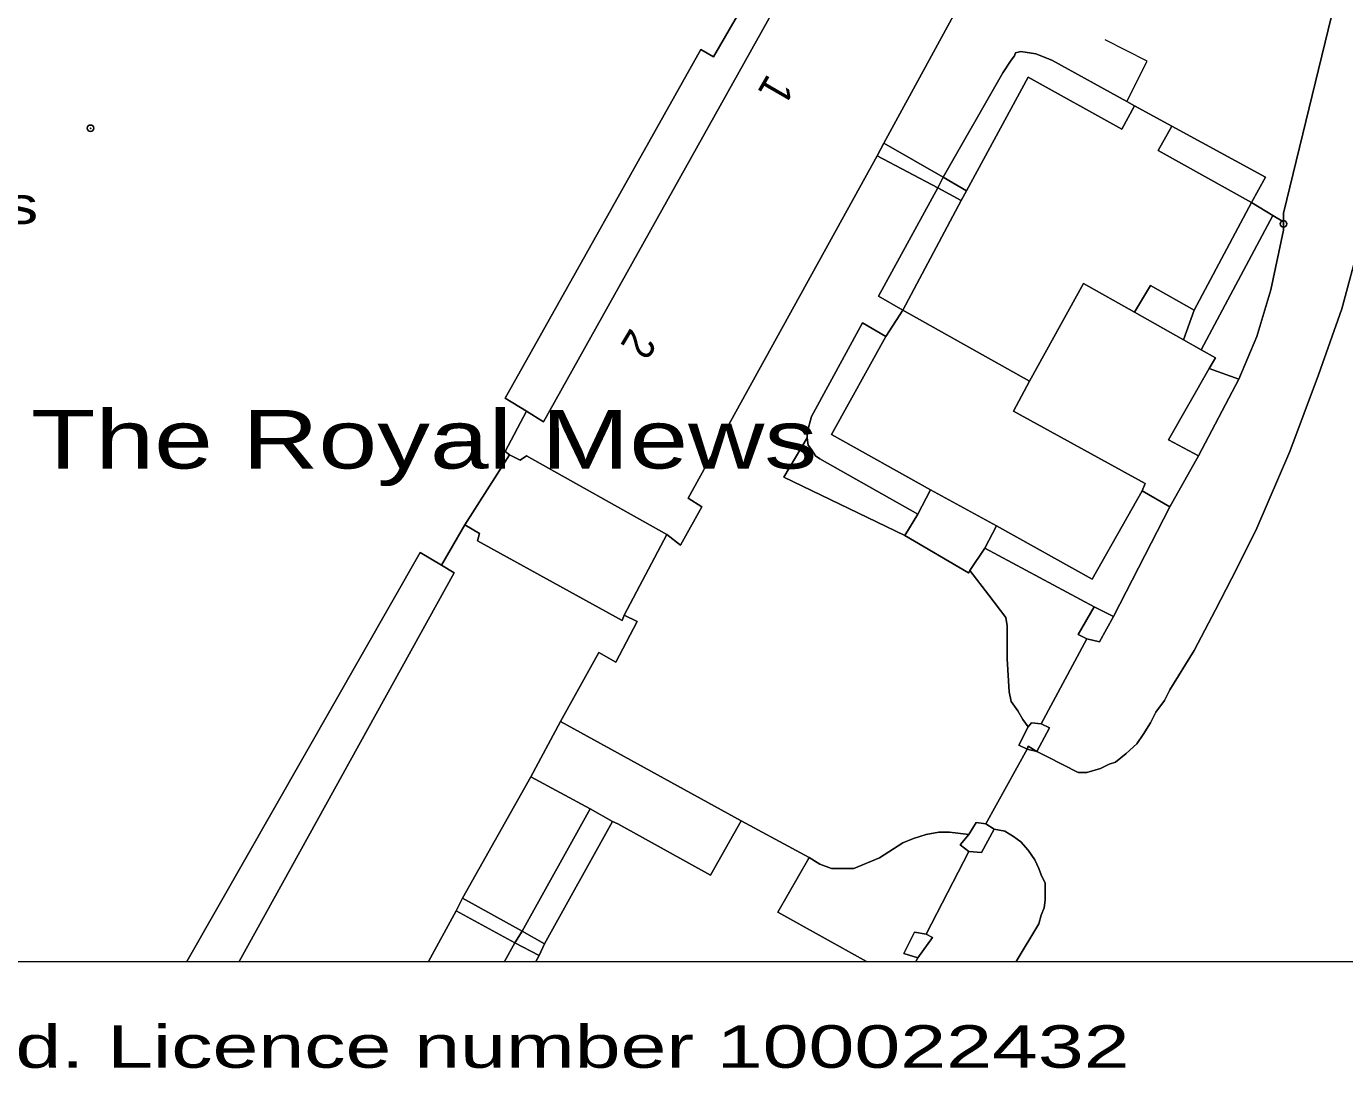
# Model space of a CAD drawing. Extents: x 528790 to 529292, y 179350 to 179856.
# Drawn here: x 528898.3 to 528960.3, y 179350.4 to 179400 of the extents above; entities that cross this region are included whole.
import ezdxf

# ---------------------------------------------------------------- set-up
doc = ezdxf.new("R2010")
doc.units = 0
doc.header["$LTSCALE"] = 0.6
doc.header["$PDMODE"] = 32
doc.header["$PDSIZE"] = 0.3
for name, color, linetype, lineweight in [('1', 7, 'Continuous', 13), ('2', 7, 'Continuous', 13), ('7', 7, 'Continuous', 13)]:
    doc.layers.add(name, color=color, linetype=linetype, lineweight=lineweight)
for name, color, linetype in [('3', 7, 'Continuous'), ('4', 7, 'Continuous'), ('5', 7, 'Continuous'), ('8', 7, 'Continuous')]:
    doc.layers.add(name, color=color, linetype=linetype)

msp = doc.modelspace()

# ---------------------------------------------------------------- linework, layer by layer
at = {"layer": '1'}
for points in [[(528897.956, 179356.024), (528905.826, 179356.024), (528916.8, 179375.25), (528917.8, 179374.65), (528918.9, 179376.55), (528921, 179379.85), (528920.8, 179380), (528921.8, 179381.9), (528920.8, 179382.5), (528930, 179398.9), (528930.6, 179398.55), (528931.9, 179400.8), (528911.446, 179412.309), (528912.253, 179413.743), (528911.257, 179414.303), (528910.45, 179412.87), (528908.12, 179408.74), (528900.05, 179413.29), (528902.38, 179417.42), (528903.061, 179418.631), (528902.369, 179419.02), (528901.688, 179417.809), (528881.8, 179429)], [(528943, 179402.55), (528938.6, 179394.5), (528941.4, 179392.9), (528944.2, 179397.8), (528944.6, 179398.4), (528944.75, 179398.6), (528944.8, 179398.75), (528945.05, 179398.8), (528945.75, 179398.7), (528946.5, 179398.4), (528950.029, 179396.454), (528950.4, 179396.25), (528952.15, 179395.3), (528956.55, 179392.9), (528955.9, 179391.7), (528956.903, 179391.098), (528957.4, 179390.8), (528957.4, 179391.2), (528959.95, 179401.7)], [(528959.95, 179401.7), (528957.4, 179391.2), (528957.4, 179390.8), (528957.4, 179390.4), (528956.8, 179387.6), (528956.15, 179385.4), (528955.3, 179383.4), (528953.4, 179379.8), (528952.05, 179377.4), (528949.4, 179372.25), (528948.75, 179371.05), (528948.15, 179371.2), (528946, 179367.2), (528946.4, 179367), (528945.8, 179365.9), (528946.3, 179365.65), (528947.75, 179364.9), (528948.15, 179364.9), (528948.8, 179365.1), (528949.2, 179365.3), (528949.5, 179365.4), (528950, 179365.8), (528950.5, 179366.25), (528950.8, 179366.7), (528951.15, 179367.25), (528951.4, 179367.75), (528951.8, 179368.3), (528952.05, 179368.8), (528953.2, 179370.65), (528954.2, 179372.55), (528955.2, 179374.5), (528956.15, 179376.4), (528957.7, 179380), (528959.05, 179383.6), (528960.15, 179386.7), (528961, 179389.9)], [(528961, 179389.9), (528960.15, 179386.7), (528959.05, 179383.6), (528957.7, 179380), (528956.15, 179376.4), (528955.2, 179374.5), (528954.2, 179372.55), (528953.2, 179370.65), (528952.05, 179368.8), (528951.8, 179368.3), (528951.4, 179367.75), (528951.15, 179367.25), (528950.8, 179366.7), (528950.5, 179366.25), (528950, 179365.8), (528949.5, 179365.4), (528949.2, 179365.3), (528948.8, 179365.1), (528948.15, 179364.9), (528947.75, 179364.9), (528946.3, 179365.65), (528945.8, 179365.9), (528945.35, 179366), (528943.4, 179362.5), (528943.8, 179362.25), (528944.3, 179362.15), (528944.7, 179361.9), (528945.05, 179361.65), (528945.4, 179361.25), (528945.7, 179360.8), (528945.9, 179360.4), (528946, 179360.1), (528946.2, 179359.7), (528946.2, 179358.9), (528946.15, 179358.55), (528946, 179358.2), (528945.9, 179357.8), (528944.836, 179356.024), (528961.131, 179356.024)]]:
    msp.add_lwpolyline(points, dxfattribs=at)
for points in [[(528938.3, 179393.9), (528938.6, 179394.5), (528943, 179402.55), (528942.6, 179402.8), (528936.95, 179405.85), (528936.4, 179406.15), (528935.95, 179405.3), (528922.6, 179381.4), (528921.8, 179381.9), (528920.8, 179380), (528921, 179379.85), (528921.5, 179379.6), (528921.8, 179379.8), (528928.4, 179376.1), (528929.05, 179375.6), (528930.05, 179377.4), (528929.4, 179377.8)], [(528921.8, 179381.9), (528922.6, 179381.4), (528935.95, 179405.3), (528934.8, 179405.95), (528931.9, 179400.8), (528930.6, 179398.55), (528930, 179398.9), (528920.8, 179382.5)], [(528950.4, 179396.25), (528950.029, 179396.454), (528946.5, 179398.4), (528945.75, 179398.7), (528945.05, 179398.8), (528944.8, 179398.75), (528944.75, 179398.6), (528944.6, 179398.4), (528944.2, 179397.8), (528941.4, 179392.9), (528942.5, 179392.25), (528945.4, 179397.6), (528949.8, 179395.15)], [(528945.45, 179383.3), (528948, 179387.9), (528950.4, 179386.55), (528951.15, 179387.8), (528953.2, 179386.65), (528955.9, 179391.7), (528951.5, 179394.15), (528952.15, 179395.3), (528950.4, 179396.25), (528949.8, 179395.15), (528945.4, 179397.6), (528942.5, 179392.25), (528942.25, 179391.8), (528939.5, 179386.65)], [(528952.15, 179395.3), (528951.5, 179394.15), (528955.9, 179391.7), (528956.55, 179392.9)], [(528941.4, 179392.9), (528938.6, 179394.5), (528938.3, 179393.9), (528941.15, 179392.4)], [(528939.5, 179386.65), (528938.35, 179387.3), (528941.15, 179392.4), (528938.3, 179393.9), (528929.4, 179377.8), (528930.05, 179377.4), (528929.05, 179375.6), (528928.4, 179376.1), (528926.4, 179372.3), (528927, 179372), (528926, 179370.1), (528925.2, 179370.55), (528923.4, 179367.3), (528931.899, 179362.632), (528935.088, 179360.906), (528935.6, 179360.6), (528936.15, 179360.4), (528937.2, 179360.4), (528938.4, 179360.9), (528939.5, 179361.6), (528940, 179361.8), (528940.6, 179362), (528941.2, 179362.1), (528941.7, 179362.1), (528942.6, 179362), (528942.95, 179362.55), (528943.4, 179362.5), (528945.35, 179366), (528944.95, 179366.2), (528945.4, 179367.05), (528945.15, 179367.4), (528944.9, 179367.8), (528944.6, 179368.25), (528944.5, 179368.7), (528944.4, 179370.25), (528944.4, 179371.8), (528944.35, 179372.2), (528943.55, 179373.25), (528942.65, 179374.4), (528942.6, 179374.3), (528942.594, 179374.303), (528939.6, 179376.05), (528933.9, 179378.8), (528935, 179380.65), (528935, 179380.9), (528935.2, 179381.65), (528937.6, 179386.05), (528938.7, 179385.4)], [(528941.15, 179392.4), (528942.25, 179391.8), (528942.5, 179392.25), (528941.4, 179392.9)], [(528941.15, 179392.4), (528938.35, 179387.3), (528939.5, 179386.65), (528942.25, 179391.8)], [(528956.903, 179391.098), (528955.9, 179391.7), (528953.2, 179386.65), (528952.7, 179385.25), (528953.532, 179384.778)], [(528955.3, 179383.4), (528956.15, 179385.4), (528956.8, 179387.6), (528957.4, 179390.4), (528957.4, 179390.8), (528956.903, 179391.098), (528953.532, 179384.778), (528954.2, 179384.4), (528953.9, 179383.9)], [(528950.4, 179386.55), (528948, 179387.9), (528945.45, 179383.3), (528944.7, 179381.9), (528950.9, 179378.5), (528950.75, 179378.15), (528952.05, 179377.4), (528953.4, 179379.8), (528952, 179380.55), (528953.9, 179383.9), (528954.2, 179384.4), (528953.532, 179384.778), (528952.7, 179385.25)], [(528953.2, 179386.65), (528951.15, 179387.8), (528950.4, 179386.55), (528952.7, 179385.25)], [(528950.75, 179378.15), (528950.9, 179378.5), (528944.7, 179381.9), (528945.45, 179383.3), (528939.5, 179386.65), (528938.7, 179385.4), (528936.15, 179380.8), (528940.8, 179378.2), (528943.9, 179376.5), (528948.4, 179374)], [(528935, 179380.65), (528935.05, 179380.3), (528935.2, 179380.1), (528935.4, 179379.8), (528935.6, 179379.65), (528940.2, 179377.05), (528940.8, 179378.2), (528936.15, 179380.8), (528938.7, 179385.4), (528937.6, 179386.05), (528935.2, 179381.65), (528935, 179380.9)], [(528955.3, 179383.4), (528953.9, 179383.9), (528952, 179380.55), (528953.4, 179379.8)], [(528940.2, 179377.05), (528935.6, 179379.65), (528935.4, 179379.8), (528935.2, 179380.1), (528935.05, 179380.3), (528935, 179380.65), (528933.9, 179378.8), (528939.6, 179376.05)], [(528928.4, 179376.1), (528921.8, 179379.8), (528921.5, 179379.6), (528921, 179379.85), (528918.9, 179376.55), (528919.6, 179376.15), (528919.5, 179375.8), (528926.3, 179372.05), (528926.4, 179372.3)], [(528942.65, 179374.4), (528943.35, 179375.45), (528943.9, 179376.5), (528940.8, 179378.2), (528940.2, 179377.05), (528939.6, 179376.05), (528942.594, 179374.303), (528942.6, 179374.3)], [(528943.9, 179376.5), (528943.35, 179375.45), (528948.5, 179372.7), (528949.4, 179372.25), (528952.05, 179377.4), (528950.75, 179378.15), (528948.4, 179374)], [(528908.296, 179356.024), (528917.199, 179356.024), (528918.5, 179358.4), (528918.8, 179359), (528922, 179364.7), (528923.4, 179367.3), (528925.2, 179370.55), (528926, 179370.1), (528927, 179372), (528926.4, 179372.3), (528926.3, 179372.05), (528919.5, 179375.8), (528919.6, 179376.15), (528918.9, 179376.55), (528917.8, 179374.65), (528918.4, 179374.3)], [(528908.296, 179356.024), (528918.4, 179374.3), (528917.8, 179374.65), (528916.8, 179375.25), (528905.826, 179356.024)], [(528948.5, 179372.7), (528943.35, 179375.45), (528942.65, 179374.4), (528943.55, 179373.25), (528944.35, 179372.2), (528944.4, 179371.8), (528944.4, 179370.25), (528944.5, 179368.7), (528944.6, 179368.25), (528944.9, 179367.8), (528945.15, 179367.4), (528945.4, 179367.05), (528945.55, 179367.25), (528946, 179367.2), (528948.15, 179371.2), (528947.75, 179371.4)], [(528948.15, 179371.2), (528948.75, 179371.05), (528949.4, 179372.25), (528948.5, 179372.7), (528947.75, 179371.4)], [(528931.899, 179362.632), (528923.4, 179367.3), (528922, 179364.7), (528924.8, 179363.2), (528925.85, 179362.6), (528926.1, 179362.5), (528930.459, 179360.087)], [(528945.35, 179366), (528945.4, 179366.15), (528945.8, 179365.9), (528946.4, 179367), (528946, 179367.2), (528945.55, 179367.25), (528945.4, 179367.05), (528944.95, 179366.2)], [(528945.8, 179365.9), (528945.4, 179366.15), (528945.35, 179366)], [(528924.8, 179363.2), (528922, 179364.7), (528918.8, 179359), (528921.6, 179357.45)], [(528924.8, 179363.2), (528921.6, 179357.45), (528922.65, 179356.85), (528925.85, 179362.6)], [(528937.795, 179356.024), (528933.624, 179358.334), (528935.077, 179360.887), (528935.088, 179360.906), (528931.899, 179362.632), (528930.459, 179360.087), (528926.1, 179362.5), (528925.85, 179362.6), (528922.65, 179356.85), (528922.4, 179356.3), (528922.248, 179356.024)], [(528937.795, 179356.024), (528940.105, 179356.024), (528940.2, 179356.2), (528939.55, 179356.4), (528940.05, 179357.4), (528940.6, 179357.3), (528942.6, 179361.2), (528942.2, 179361.5), (528942.6, 179362), (528941.7, 179362.1), (528941.2, 179362.1), (528940.6, 179362), (528940, 179361.8), (528939.5, 179361.6), (528938.4, 179360.9), (528937.2, 179360.4), (528936.15, 179360.4), (528935.6, 179360.6), (528935.088, 179360.906), (528935.077, 179360.887), (528933.624, 179358.334)], [(528944.836, 179356.024), (528945.9, 179357.8), (528946, 179358.2), (528946.15, 179358.55), (528946.2, 179358.9), (528946.2, 179359.7), (528946, 179360.1), (528945.9, 179360.4), (528945.7, 179360.8), (528945.4, 179361.25), (528945.05, 179361.65), (528944.7, 179361.9), (528944.3, 179362.15), (528943.8, 179362.25), (528943.2, 179361.15), (528942.6, 179361.2), (528940.6, 179357.3), (528940.9, 179357.15), (528940.2, 179356.2), (528940.105, 179356.024)], [(528943.4, 179362.5), (528942.95, 179362.55), (528942.6, 179362), (528942.2, 179361.5), (528942.6, 179361.2), (528943.2, 179361.15), (528943.8, 179362.25)], [(528918.5, 179358.4), (528921.25, 179356.9), (528921.6, 179357.45), (528918.8, 179359)], [(528920.764, 179356.024), (528921.25, 179356.9), (528918.5, 179358.4), (528917.199, 179356.024)], [(528922.4, 179356.3), (528922.65, 179356.85), (528921.6, 179357.45), (528921.25, 179356.9)], [(528940.2, 179356.2), (528940.9, 179357.15), (528940.6, 179357.3), (528940.05, 179357.4), (528939.55, 179356.4)], [(528920.764, 179356.024), (528922.248, 179356.024), (528922.4, 179356.3), (528921.25, 179356.9)]]:
    msp.add_lwpolyline(points, close=True, dxfattribs=at)
at = {"layer": '2'}
for p, q in [((528950.029, 179396.454), (528950.4, 179396.25)), ((528952.15, 179395.3), (528950.4, 179396.25)), ((528938.6, 179394.5), (528938.3, 179393.9)), ((528938.6, 179394.5), (528941.4, 179392.9)), ((528938.3, 179393.9), (528941.15, 179392.4)), ((528941.15, 179392.4), (528941.4, 179392.9)), ((528941.4, 179392.9), (528942.5, 179392.25)), ((528942.25, 179391.8), (528939.5, 179386.65)), ((528941.15, 179392.4), (528942.25, 179391.8)), ((528942.5, 179392.25), (528942.25, 179391.8)), ((528953.2, 179386.65), (528955.9, 179391.7)), ((528955.9, 179391.7), (528956.903, 179391.098)), ((528953.532, 179384.778), (528956.903, 179391.098)), ((528956.903, 179391.098), (528957.4, 179390.8)), ((528939.5, 179386.65), (528938.7, 179385.4)), ((528945.45, 179383.3), (528939.5, 179386.65)), ((528952.7, 179385.25), (528950.4, 179386.55)), ((528953.2, 179386.65), (528952.7, 179385.25)), ((528953.532, 179384.778), (528952.7, 179385.25)), ((528953.9, 179383.9), (528955.3, 179383.4)), ((528955.3, 179383.4), (528953.4, 179379.8)), ((528918.9, 179376.55), (528921, 179379.85)), ((528953.4, 179379.8), (528952.05, 179377.4)), ((528940.8, 179378.2), (528940.2, 179377.05)), ((528940.8, 179378.2), (528943.9, 179376.5)), ((528950.75, 179378.15), (528952.05, 179377.4)), ((528940.2, 179377.05), (528939.6, 179376.05)), ((528952.05, 179377.4), (528949.4, 179372.25)), ((528917.8, 179374.65), (528918.9, 179376.55)), ((528943.35, 179375.45), (528943.9, 179376.5)), ((528928.4, 179376.1), (528926.4, 179372.3)), ((528942.65, 179374.4), (528943.35, 179375.45)), ((528948.5, 179372.7), (528943.35, 179375.45)), ((528949.4, 179372.25), (528948.5, 179372.7)), ((528948.15, 179371.2), (528946, 179367.2)), ((528923.4, 179367.3), (528922, 179364.7)), ((528923.4, 179367.3), (528931.899, 179362.632)), ((528945.35, 179366), (528943.4, 179362.5)), ((528945.8, 179365.9), (528945.35, 179366)), ((528922, 179364.7), (528918.8, 179359)), ((528922, 179364.7), (528924.8, 179363.2)), ((528921.6, 179357.45), (528924.8, 179363.2)), ((528924.8, 179363.2), (528925.85, 179362.6)), ((528925.85, 179362.6), (528922.65, 179356.85)), ((528931.899, 179362.632), (528935.088, 179360.906)), ((528943.4, 179362.5), (528943.8, 179362.25)), ((528942.6, 179361.2), (528940.6, 179357.3)), ((528918.8, 179359), (528918.5, 179358.4)), ((528918.8, 179359), (528921.6, 179357.45)), ((528918.5, 179358.4), (528917.199, 179356.024)), ((528918.5, 179358.4), (528921.25, 179356.9)), ((528921.25, 179356.9), (528921.6, 179357.45)), ((528921.6, 179357.45), (528922.65, 179356.85)), ((528920.764, 179356.024), (528921.25, 179356.9)), ((528921.25, 179356.9), (528922.4, 179356.3)), ((528922.65, 179356.85), (528922.4, 179356.3)), ((528922.4, 179356.3), (528922.248, 179356.024)), ((528940.2, 179356.2), (528940.105, 179356.024))]:
    msp.add_line(p, q, dxfattribs=at)
for points in [[(528921.8, 179381.9), (528922.6, 179381.4), (528935.95, 179405.3)], [(528942.6, 179402.8), (528943, 179402.55), (528938.6, 179394.5)], [(528959.95, 179401.7), (528957.4, 179391.2), (528957.4, 179390.8)], [(528921.8, 179381.9), (528920.8, 179382.5), (528930, 179398.9), (528930.6, 179398.55), (528931.9, 179400.8)], [(528950.029, 179396.454), (528950.985, 179398.357), (528949.008, 179399.36)], [(528941.4, 179392.9), (528944.2, 179397.8), (528944.6, 179398.4), (528944.75, 179398.6), (528944.8, 179398.75), (528945.05, 179398.8), (528945.75, 179398.7), (528946.5, 179398.4), (528950.029, 179396.454)], [(528950.4, 179396.25), (528949.8, 179395.15), (528945.4, 179397.6), (528942.5, 179392.25)], [(528955.9, 179391.7), (528951.5, 179394.15), (528952.15, 179395.3)], [(528952.15, 179395.3), (528956.55, 179392.9), (528955.9, 179391.7)], [(528938.3, 179393.9), (528929.4, 179377.8), (528930.05, 179377.4), (528929.05, 179375.6), (528928.4, 179376.1)], [(528939.5, 179386.65), (528938.35, 179387.3), (528941.15, 179392.4)], [(528957.4, 179390.8), (528957.4, 179390.4), (528956.8, 179387.6), (528956.15, 179385.4), (528955.3, 179383.4)], [(528961, 179389.9), (528960.15, 179386.7), (528959.05, 179383.6), (528957.7, 179380), (528956.15, 179376.4), (528955.2, 179374.5), (528954.2, 179372.55), (528953.2, 179370.65), (528952.05, 179368.8), (528951.8, 179368.3), (528951.4, 179367.75), (528951.15, 179367.25), (528950.8, 179366.7), (528950.5, 179366.25), (528950, 179365.8), (528949.5, 179365.4), (528949.2, 179365.3), (528948.8, 179365.1), (528948.15, 179364.9), (528947.75, 179364.9), (528946.3, 179365.65), (528945.8, 179365.9)], [(528950.4, 179386.55), (528948, 179387.9), (528945.45, 179383.3)], [(528950.4, 179386.55), (528951.15, 179387.8), (528953.2, 179386.65)], [(528938.7, 179385.4), (528937.6, 179386.05), (528935.2, 179381.65), (528935, 179380.9), (528935, 179380.65)], [(528938.7, 179385.4), (528936.15, 179380.8), (528940.8, 179378.2)], [(528953.9, 179383.9), (528954.2, 179384.4), (528953.532, 179384.778)], [(528953.4, 179379.8), (528952, 179380.55), (528953.9, 179383.9)], [(528945.45, 179383.3), (528944.7, 179381.9), (528950.9, 179378.5), (528950.75, 179378.15)], [(528921, 179379.85), (528920.8, 179380), (528921.8, 179381.9)], [(528935, 179380.65), (528933.9, 179378.8), (528939.6, 179376.05)], [(528935, 179380.65), (528935.05, 179380.3), (528935.2, 179380.1), (528935.4, 179379.8), (528935.6, 179379.65), (528940.2, 179377.05)], [(528928.4, 179376.1), (528921.8, 179379.8), (528921.5, 179379.6), (528921, 179379.85)], [(528943.9, 179376.5), (528948.4, 179374), (528950.75, 179378.15)], [(528918.9, 179376.55), (528919.6, 179376.15), (528919.5, 179375.8), (528926.3, 179372.05), (528926.4, 179372.3)], [(528939.6, 179376.05), (528942.594, 179374.303), (528942.6, 179374.3), (528942.65, 179374.4)], [(528905.826, 179356.024), (528916.8, 179375.25), (528917.8, 179374.65)], [(528908.296, 179356.024), (528918.4, 179374.3), (528917.8, 179374.65)], [(528945.4, 179367.05), (528945.15, 179367.4), (528944.9, 179367.8), (528944.6, 179368.25), (528944.5, 179368.7), (528944.4, 179370.25), (528944.4, 179371.8), (528944.35, 179372.2), (528943.55, 179373.25), (528942.65, 179374.4)], [(528948.15, 179371.2), (528947.75, 179371.4), (528948.5, 179372.7)], [(528926.4, 179372.3), (528927, 179372), (528926, 179370.1), (528925.2, 179370.55), (528923.4, 179367.3)], [(528949.4, 179372.25), (528948.75, 179371.05), (528948.15, 179371.2)], [(528945.4, 179367.05), (528944.95, 179366.2), (528945.35, 179366)], [(528946, 179367.2), (528945.55, 179367.25), (528945.4, 179367.05)], [(528946, 179367.2), (528946.4, 179367), (528945.8, 179365.9)], [(528945.8, 179365.9), (528945.4, 179366.15), (528945.35, 179366)], [(528925.85, 179362.6), (528926.1, 179362.5), (528930.459, 179360.087), (528931.899, 179362.632)], [(528935.088, 179360.906), (528935.6, 179360.6), (528936.15, 179360.4), (528937.2, 179360.4), (528938.4, 179360.9), (528939.5, 179361.6), (528940, 179361.8), (528940.6, 179362), (528941.2, 179362.1), (528941.7, 179362.1), (528942.6, 179362)], [(528943.4, 179362.5), (528942.95, 179362.55), (528942.6, 179362)], [(528943.8, 179362.25), (528943.2, 179361.15), (528942.6, 179361.2)], [(528943.8, 179362.25), (528944.3, 179362.15), (528944.7, 179361.9), (528945.05, 179361.65), (528945.4, 179361.25), (528945.7, 179360.8), (528945.9, 179360.4), (528946, 179360.1), (528946.2, 179359.7), (528946.2, 179358.9), (528946.15, 179358.55), (528946, 179358.2), (528945.9, 179357.8), (528944.836, 179356.024)], [(528942.6, 179362), (528942.2, 179361.5), (528942.6, 179361.2)], [(528937.795, 179356.024), (528933.624, 179358.334), (528935.077, 179360.887), (528935.088, 179360.906)], [(528940.6, 179357.3), (528940.05, 179357.4), (528939.55, 179356.4), (528940.2, 179356.2)], [(528940.6, 179357.3), (528940.9, 179357.15), (528940.2, 179356.2)]]:
    msp.add_lwpolyline(points, dxfattribs=at)
at = {"layer": '3'}
msp.add_point((528901.3, 179395.2), dxfattribs=at)
at = {"layer": '4'}
msp.add_point((528957.4, 179390.7), dxfattribs=at)
at = {"layer": '7'}
msp.add_lwpolyline([(528790.22, 179356.024), (529290.22, 179356.024), (529290.22, 179856.024), (528790.22, 179856.024)], close=True, dxfattribs=at)

# ---------------------------------------------------------------- texts
at = {"layer": '5', "width": 0.9}
for s, rotation, p in [('1', 240, (528933.15, 179397.8)), ('2', 239, (528926.7, 179385.85))]:
    msp.add_text(s, height=1.5, rotation=rotation, dxfattribs=at).set_placement(p)
at = {"layer": '5', "width": 1.35}
for s, height, p in [('Trees', 1.75, (528890.77, 179390.7)), ('The Royal Mews', 2.75, (528898.5, 179379.2))]:
    msp.add_text(s, height=height, dxfattribs=at).set_placement(p)
at = {"layer": '8', "width": 1.45}
msp.add_text('Ordnance Survey, (c) Crown Copyright 2018. All rights reserved. Licence number 100022432', height=2, dxfattribs=at).set_placement((528790.22, 179351.024))

doc.saveas('drawing.dxf')
